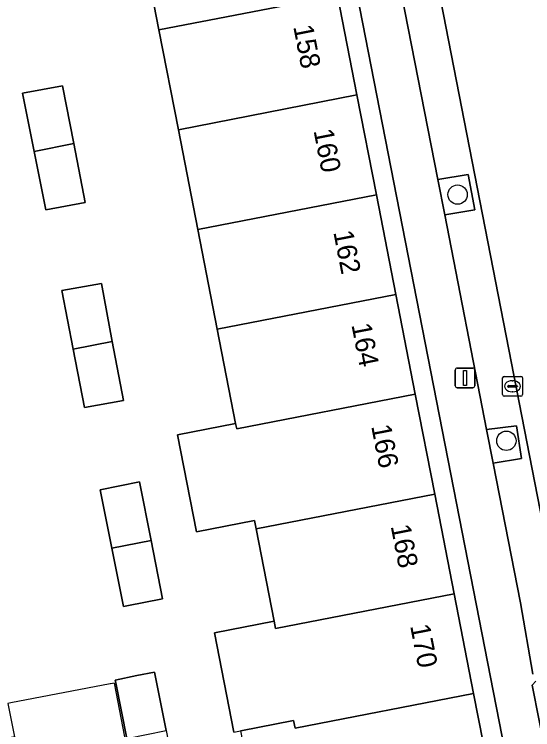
# Model space of a CAD drawing. Extents: x 160377 to 161131, y 383938 to 384853.
# Drawn here: x 160789.34 to 160815.54, y 384537.03 to 384573.2 of the extents above; entities that cross this region are included whole.
import ezdxf

# ---------------------------------------------------------------- set-up
doc = ezdxf.new("R2010")
doc.units = 0
for name, color, linetype in [('IMGEO_Boom', 7, 'Continuous'), ('IMGEO_Erf', 7, 'Continuous'), ('IMGEO_Groenvoorziening', 7, 'Continuous'), ('IMGEO_Kolk', 7, 'Continuous'), ('IMGEO_Lichtmast', 7, 'Continuous'), ('IMGEO_Pand', 7, 'Continuous'), ('IMGEO_Pand_nummerreeks', 7, 'Continuous'), ('IMGEO_Pand_overbouw', 7, 'Continuous'), ('IMGEO_Parkeervlak_open', 7, 'Continuous'), ('IMGEO_Rijbaan_lokaal_open', 7, 'Continuous'), ('IMGEO_Voetpad_open', 7, 'Continuous')]:
    doc.layers.add(name, color=color, linetype=linetype)

msp = doc.modelspace()

# ---------------------------------------------------------------- linework, layer by layer
at = {"layer": 'IMGEO_Boom'}
for centre in [(160811.748, 384564.085), (160814.213, 384551.638)]:
    msp.add_circle(centre, 0.489, dxfattribs=at)
at = {"layer": 'IMGEO_Erf'}
for points in [[(160814.707, 384533.039), (160805.221, 384581.626), (160804.227, 384586.696), (160801.827, 384589.484), (160785.555, 384608.533), (160784.593, 384609.659), (160759.221, 384639.361), (160756.612, 384642.415), (160753.096, 384646.531), (160752.089, 384647.71), (160738.611, 384663.488), (160738.585, 384663.466), (160731.208, 384657.183), (160728.177, 384654.568), (160723.454, 384650.553), (160720.379, 384647.933), (160715.683, 384643.941), (160712.616, 384641.352)], [(160800.44, 384536.909), (160799.464, 384541.925), (160802.477, 384542.511), (160801.566, 384547.189), (160801.484, 384547.612), (160798.549, 384547.041), (160797.597, 384551.934), (160800.531, 384552.506), (160799.602, 384557.277), (160798.62, 384562.321), (160797.637, 384567.365), (160796.655, 384572.409), (160795.673, 384577.454)], [(160805.677, 384574.166), (160806.66, 384569.122), (160807.644, 384564.078), (160808.627, 384559.034), (160809.61, 384553.99), (160810.594, 384548.946), (160811.577, 384543.902), (160812.56, 384538.858), (160813.543, 384533.816)]]:
    msp.add_lwpolyline(points, dxfattribs=at)
for points in [[(160789.765, 384569.221), (160791.774, 384569.589), (160792.347, 384566.665), (160792.931, 384563.682), (160790.928, 384563.32), (160790.347, 384566.271)], [(160792.316, 384556.277), (160791.739, 384559.242), (160793.746, 384559.597), (160794.297, 384556.662), (160794.858, 384553.678), (160792.892, 384553.312)], [(160793.687, 384549.15), (160795.672, 384549.556), (160796.254, 384546.599), (160796.835, 384543.651), (160795.027, 384543.288), (160794.868, 384543.256), (160794.278, 384546.203)], [(160796.43, 384539.945), (160797.012, 384536.988), (160797.593, 384534.04), (160795.626, 384533.645), (160795.036, 384536.592), (160794.473, 384539.402), (160794.445, 384539.539), (160795.541, 384539.763)]]:
    msp.add_lwpolyline(points, close=True, dxfattribs=at)
at = {"layer": 'IMGEO_Groenvoorziening'}
for points in [[(160810.749, 384564.848), (160811.098, 384563.058), (160812.623, 384563.321), (160812.277, 384565.101)], [(160813.217, 384552.203), (160813.547, 384550.512), (160814.98, 384550.736), (160814.725, 384552.401)]]:
    msp.add_lwpolyline(points, close=True, dxfattribs=at)
msp.add_lwpolyline([(160815.7, 384539.483), (160815.52, 384539.282), (160816.219, 384535.713), (160818.259, 384536.105), (160818.077, 384537.048), (160818.072, 384537.074), (160818.024, 384537.321)], dxfattribs=at)
at = {"layer": 'IMGEO_Kolk'}
for p, q in [((160814.025, 384553.969), (160814.025, 384554.821)), ((160814.1, 384554.895), (160814.952, 384554.895)), ((160814.513, 384554.675), (160814.538, 384554.675)), ((160815.026, 384554.821), (160815.026, 384553.969)), ((160814.284, 384554.389), (160814.284, 384554.401)), ((160814.722, 384554.352), (160814.324, 384554.352)), ((160814.327, 384554.438), (160814.725, 384554.438)), ((160814.768, 384554.401), (160814.768, 384554.389)), ((160814.536, 384554.115), (160814.511, 384554.115)), ((160814.952, 384553.895), (160814.1, 384553.895))]:
    msp.add_line(p, q, dxfattribs=at)
for points in [[(160814.025, 384553.969), (160814.025, 384554.821)], [(160814.1, 384554.895), (160814.952, 384554.895)], [(160815.026, 384554.821), (160815.026, 384553.969)], [(160814.952, 384553.895), (160814.1, 384553.895)]]:
    msp.add_lwpolyline(points, dxfattribs=at)
for centre, radius, start, end in [((160814.102, 384554.819), 0.0765, 91.552, 178.448), ((160814.102, 384554.819), 0.0765, 91.552, 178.448), ((160814.95, 384554.819), 0.0765, 1.552, 88.448), ((160814.95, 384554.819), 0.0765, 1.552, 88.448), ((160814.324, 384554.398), 0.0403, 85.8775, 175.7526), ((160814.321, 384554.388), 0.0366, 178.938, 274.7102), ((160814.725, 384554.395), 0.043, 264.8664, 352.4533), ((160814.729, 384554.4), 0.0386, 1.7309, 96.639), ((160814.102, 384553.971), 0.0765, 181.552, 268.448), ((160814.102, 384553.971), 0.0765, 181.552, 268.448), ((160814.95, 384553.971), 0.0765, 271.552, 358.448), ((160814.95, 384553.971), 0.0765, 271.552, 358.448)]:
    msp.add_arc(centre, radius, start, end, dxfattribs=at)
for centre, major_axis, ratio, start_param, end_param in [((160814.512, 384554.395), (-0.387, 0.002), 0.722429, 4.712389, 7.853982), ((160814.537, 384554.395), (-0.39, 0.002), 0.717154, 1.570796, 4.712389)]:
    msp.add_ellipse(centre, major_axis=major_axis, ratio=ratio, start_param=start_param, end_param=end_param, dxfattribs=at)
at = {"layer": 'IMGEO_Lichtmast'}
for p, q in [((160811.629, 384554.415), (160811.629, 384555.215)), ((160811.629, 384555.215), (160811.629, 384554.415)), ((160811.729, 384555.315), (160812.519, 384555.315)), ((160812.519, 384555.315), (160811.729, 384555.315)), ((160812.619, 384555.215), (160812.619, 384554.415)), ((160812.619, 384554.415), (160812.619, 384555.215)), ((160812.519, 384554.315), (160811.729, 384554.315)), ((160811.729, 384554.315), (160812.519, 384554.315))]:
    msp.add_line(p, q, dxfattribs=at)
msp.add_lwpolyline([(160812.049, 384555.19), (160812.199, 384555.19), (160812.199, 384554.44), (160812.049, 384554.44), (160812.049, 384555.19)], dxfattribs=at)
for centre, start, end in [((160811.729, 384555.215), 90, 180), ((160811.729, 384555.215), 90, 180), ((160812.519, 384555.215), 0, 90), ((160812.519, 384555.215), 360, 90), ((160811.729, 384554.415), 180, 270), ((160811.729, 384554.415), 180, 270), ((160812.519, 384554.415), 270, 0), ((160812.519, 384554.415), 270, 0)]:
    msp.add_arc(centre, 0.1, start, end, dxfattribs=at)
at = {"layer": 'IMGEO_Pand'}
for points in [[(160804.705, 384579.154), (160795.673, 384577.454), (160796.655, 384572.409), (160805.677, 384574.166)], [(160805.677, 384574.166), (160796.655, 384572.409), (160797.637, 384567.365), (160806.66, 384569.122)], [(160789.765, 384569.221), (160790.347, 384566.271), (160792.347, 384566.665), (160791.774, 384569.589)], [(160806.66, 384569.122), (160797.637, 384567.365), (160798.62, 384562.321), (160807.644, 384564.078)], [(160792.347, 384566.665), (160790.347, 384566.271), (160790.928, 384563.32), (160792.931, 384563.682)], [(160807.644, 384564.078), (160798.62, 384562.321), (160799.602, 384557.277), (160808.627, 384559.034)], [(160791.739, 384559.242), (160792.316, 384556.277), (160794.297, 384556.662), (160793.746, 384559.597)], [(160808.627, 384559.034), (160799.602, 384557.277), (160800.531, 384552.506), (160800.584, 384552.233), (160809.61, 384553.99)], [(160794.297, 384556.662), (160792.316, 384556.277), (160792.892, 384553.312), (160794.858, 384553.678)], [(160809.61, 384553.99), (160800.584, 384552.233), (160800.531, 384552.506), (160797.597, 384551.934), (160798.549, 384547.041), (160801.484, 384547.612), (160801.566, 384547.189), (160810.594, 384548.946)], [(160793.687, 384549.15), (160794.278, 384546.203), (160796.254, 384546.599), (160795.672, 384549.556)], [(160810.594, 384548.946), (160801.566, 384547.189), (160802.477, 384542.511), (160802.549, 384542.144), (160811.577, 384543.902)], [(160796.254, 384546.599), (160794.278, 384546.203), (160794.868, 384543.256), (160795.027, 384543.288), (160796.835, 384543.651)], [(160811.577, 384543.902), (160802.549, 384542.144), (160802.477, 384542.511), (160799.464, 384541.925), (160800.44, 384536.909), (160800.775, 384536.974), (160800.799, 384536.979), (160803.454, 384537.496), (160803.531, 384537.1), (160812.56, 384538.858)], [(160796.43, 384539.945), (160795.541, 384539.763), (160794.445, 384539.539), (160794.473, 384539.402), (160795.036, 384536.592), (160797.012, 384536.988)], [(160812.56, 384538.858), (160803.531, 384537.1), (160803.454, 384537.496), (160800.799, 384536.979), (160800.775, 384536.974), (160801.811, 384531.653), (160804.49, 384532.174), (160804.513, 384532.056), (160813.236, 384533.756), (160813.543, 384533.816)]]:
    msp.add_lwpolyline(points, close=True, dxfattribs=at)
at = {"layer": 'IMGEO_Pand_overbouw'}
msp.add_lwpolyline([(160794.403, 384539.388), (160794.207, 384539.35), (160794.188, 384539.346), (160789.17, 384538.383), (160789.024, 384538.355), (160789.351, 384536.674), (160786.401, 384536.102), (160787.824, 384528.813), (160790.756, 384529.385), (160790.146, 384532.577), (160795.526, 384533.606)], close=True, dxfattribs=at)
at = {"layer": 'IMGEO_Parkeervlak_open'}
for points in [[(160818.024, 384537.321), (160808.395, 384586.778)], [(160807.162, 384583.224), (160808.442, 384576.668), (160809.961, 384576.919), (160810.2, 384575.304), (160808.747, 384575.103), (160810.749, 384564.848), (160812.277, 384565.101), (160812.623, 384563.321), (160811.098, 384563.058), (160813.217, 384552.203), (160814.725, 384552.401), (160814.98, 384550.736), (160813.547, 384550.512), (160814.928, 384543.438), (160815.544, 384539.832)]]:
    msp.add_lwpolyline(points, dxfattribs=at)
at = {"layer": 'IMGEO_Rijbaan_lokaal_open'}
msp.add_lwpolyline([(160808.366, 384586.942), (160808.395, 384586.778), (160818.024, 384537.321), (160818.072, 384537.074), (160822.974, 384538.097), (160822.812, 384538.963), (160822.804, 384539.013), (160822.798, 384539.063), (160819.766, 384555.429), (160819.757, 384555.467), (160819.748, 384555.505), (160819.712, 384555.773), (160819.668, 384555.994), (160818.573, 384561.931), (160818.551, 384562.065), (160814.64, 384583.89)], dxfattribs=at)
at = {"layer": 'IMGEO_Voetpad_open'}
for points in [[(160745.948, 384658.713), (160745.656, 384658.636), (160741.646, 384663.363), (160743.2, 384664.676), (160741.8, 384666.319), (160738.611, 384663.488), (160752.089, 384647.71), (160753.096, 384646.531), (160756.612, 384642.415), (160759.221, 384639.361), (160784.593, 384609.659), (160785.555, 384608.533), (160801.827, 384589.484), (160804.227, 384586.696), (160805.221, 384581.626), (160814.707, 384533.039), (160818.393, 384535.428), (160818.27, 384536.051), (160818.259, 384536.105), (160816.219, 384535.713), (160815.52, 384539.282), (160815.7, 384539.483)], [(160815.544, 384539.832), (160814.928, 384543.438), (160813.547, 384550.512), (160813.217, 384552.203), (160811.098, 384563.058), (160810.749, 384564.848), (160808.747, 384575.103), (160808.442, 384576.668), (160807.162, 384583.224)]]:
    msp.add_lwpolyline(points, dxfattribs=at)

# ---------------------------------------------------------------- texts
at = {"layer": 'IMGEO_Pand_nummerreeks'}
for s, p in [('158', (160803.439, 384572.58)), ('160', (160804.464, 384567.321)), ('162', (160805.465, 384562.187)), ('164', (160806.379, 384557.5)), ('166', (160807.378, 384552.376)), ('168', (160808.363, 384547.324)), ('170', (160809.346, 384542.28))]:
    msp.add_text(s, height=1, rotation=281.0292, dxfattribs=at).set_placement(p)

doc.saveas('drawing.dxf')
